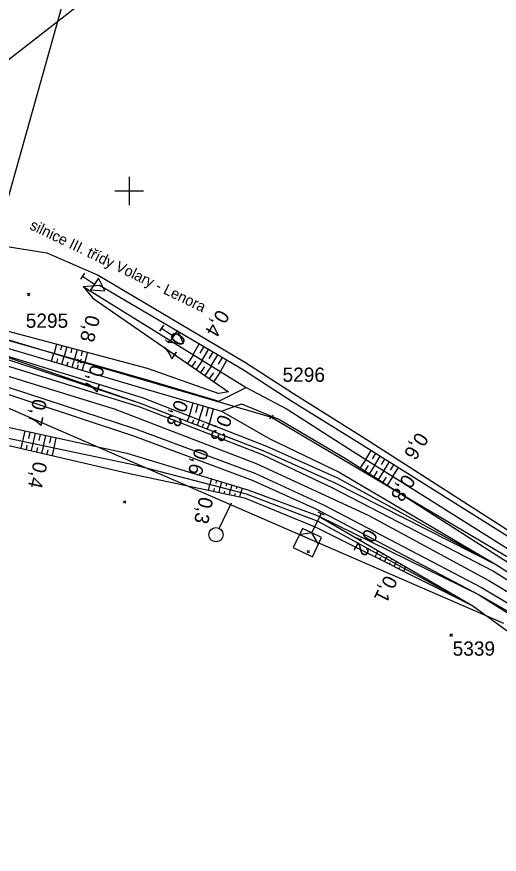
# Model space of a CAD drawing. Extents: x -804899 to -803847, y -1165742 to -1164942.
# Drawn here: x -804715.8 to -804648, y -1165193.1 to -1165075.5 of the extents above; entities that cross this region are included whole.
import ezdxf

# ---------------------------------------------------------------- set-up
doc = ezdxf.new("R2010")
doc.units = 0
for name, color, linetype in [('0381KM061-064P - Vrstva 1', 7, 'Continuous'), ('0381KM061-064P - Vrstva 36', 7, 'Continuous'), ('0381KM061-064P - Vrstva 4', 7, 'Continuous'), ('0381KM061-064P - Vrstva 48', 7, 'Continuous'), ('0381KM061-064P - Vrstva 49', 7, 'Continuous'), ('0381KM061-064P - Vrstva 51', 7, 'Continuous'), ('0381KM061-064P - Vrstva 55', 7, 'Continuous'), ('0381KM061-064P - Vrstva 7', 7, 'Continuous'), ('0381KM061-064P - Vrstva 8', 7, 'Continuous'), ('krizky_1000 - Vrstva 1', 7, 'Continuous'), ('szdc - hran DP', 7, 'Continuous'), ('szdc - szdc_cislo', 7, 'Continuous'), ('szdc - szdc_krizek', 7, 'Continuous')]:
    doc.layers.add(name, color=color, linetype=linetype)

msp = doc.modelspace()

# ---------------------------------------------------------------- linework, layer by layer
at = {"layer": '0381KM061-064P - Vrstva 1'}
for points in [[(-804748.02, -1165118.72), (-804737.69, -1165120.7), (-804722.06, -1165124.43), (-804702.11, -1165130.56), (-804682.19, -1165138.24), (-804666.44, -1165145.5)], [(-804666.44, -1165145.5), (-804649.48, -1165154.65), (-804645.14, -1165157.27), (-804633.7, -1165164.38), (-804619.36, -1165173.74)]]:
    msp.add_lwpolyline(points, dxfattribs=at)
at = {"layer": '0381KM061-064P - Vrstva 36'}
for p, q in [((-804687.37, -1165147.34), (-804685.62, -1165143.74)), ((-804687.81, -1165148.24), (-804687.81, -1165148.24))]:
    msp.add_line(p, q, dxfattribs=at)
msp.add_circle((-804687.81, -1165148.24), 1, dxfattribs=at)
at = {"layer": '0381KM061-064P - Vrstva 4'}
for points in [[(-804755.73, -1165115.93), (-804748.17, -1165116.91), (-804721.25, -1165123.25), (-804698.66, -1165130.22), (-804681.33, -1165136.99), (-804671.47, -1165141.65), (-804648.84, -1165153.36), (-804638.11, -1165160.03), (-804624.48, -1165168.7), (-804602.56, -1165183.07), (-804574.47, -1165201.72), (-804542.72, -1165222.84), (-804507.36, -1165246.55), (-804477.08, -1165266.82), (-804448.75, -1165285.88), (-804421.18, -1165304.15), (-804392.89, -1165323.09), (-804369.85, -1165338.37), (-804348.86, -1165352.04), (-804325.13, -1165367.98), (-804299.32, -1165385.27), (-804266.05, -1165407.31), (-804234.28, -1165428.6)], [(-804755.73, -1165115.93), (-804748.03, -1165116.49), (-804721.05, -1165122.36), (-804698.44, -1165129.77), (-804680.98, -1165136.5), (-804671.21, -1165140.89), (-804648.42, -1165152.46), (-804637.55, -1165159.43), (-804624.04, -1165168.29), (-804602.25, -1165182.38), (-804573.74, -1165201.2), (-804542.46, -1165222.56), (-804507.06, -1165246.03), (-804476.47, -1165266.24), (-804448.31, -1165285.08), (-804421.02, -1165303.1), (-804392.59, -1165322.59), (-804369.41, -1165337.65), (-804348.68, -1165351.59), (-804324.76, -1165367.42), (-804298.9, -1165384.42), (-804265.65, -1165406.5), (-804234.05, -1165428.04)], [(-804760.26, -1165118.8), (-804748.36, -1165120.01), (-804721.79, -1165126), (-804699.13, -1165133.38), (-804682.38, -1165139.58), (-804672.62, -1165144.09), (-804650.43, -1165155.7), (-804639.38, -1165162.29), (-804626.13, -1165170.89), (-804604.37, -1165185.52), (-804576.36, -1165204.15)], [(-804760.26, -1165118.8), (-804748.39, -1165120.75), (-804721.77, -1165126.98), (-804699.38, -1165134.38), (-804682.72, -1165140.57), (-804673.68, -1165144.67), (-804650.96, -1165156.64), (-804639.65, -1165163.02), (-804626.64, -1165171.43)]]:
    msp.add_lwpolyline(points, dxfattribs=at)
at = {"layer": '0381KM061-064P - Vrstva 48'}
for p, q in [((-804710.21, -1165121.48), (-804710.55, -1165122.77)), ((-804709.48, -1165121.67), (-804709.66, -1165122.33)), ((-804708.76, -1165121.87), (-804709.11, -1165123.18)), ((-804708.03, -1165122.06), (-804708.21, -1165122.72)), ((-804707.31, -1165122.25), (-804707.66, -1165123.59)), ((-804691.03, -1165122.96), (-804690.15, -1165121.47)), ((-804690.04, -1165122.75), (-804689.51, -1165121.85)), ((-804689.75, -1165123.74), (-804688.86, -1165122.23)), ((-804710.9, -1165123.89), (-804710.57, -1165122.77)), ((-804710.18, -1165124.1), (-804710.01, -1165123.54)), ((-804709.46, -1165124.31), (-804709.13, -1165123.18)), ((-804708.02, -1165124.74), (-804707.68, -1165123.59)), ((-804706.58, -1165122.44), (-804706.76, -1165123.12)), ((-804705.86, -1165122.63), (-804706.22, -1165124)), ((-804690.99, -1165122.98), (-804691.83, -1165124.19)), ((-804688.75, -1165123.53), (-804688.21, -1165122.61)), ((-804688.47, -1165124.53), (-804687.57, -1165122.99)), ((-804687.47, -1165124.3), (-804686.92, -1165123.37)), ((-804708.74, -1165124.53), (-804708.57, -1165123.96)), ((-804707.31, -1165124.95), (-804707.13, -1165124.37)), ((-804706.59, -1165125.17), (-804706.24, -1165124)), ((-804690.7, -1165123.87), (-804691.22, -1165124.62)), ((-804689.72, -1165123.76), (-804690.6, -1165125.04)), ((-804689.44, -1165124.68), (-804689.98, -1165125.47)), ((-804688.44, -1165124.55), (-804689.36, -1165125.9)), ((-804687.2, -1165125.32), (-804686.28, -1165123.75)), ((-804688.18, -1165125.5), (-804688.75, -1165126.32)), ((-804687.16, -1165125.34), (-804688.13, -1165126.75)), ((-804691.55, -1165131.57), (-804691.02, -1165129.73)), ((-804690.63, -1165131.08), (-804690.3, -1165129.93)), ((-804690.15, -1165132.12), (-804689.58, -1165130.14)), ((-804689.21, -1165131.58), (-804688.85, -1165130.35)), ((-804688.74, -1165132.67), (-804688.14, -1165130.56)), ((-804691.55, -1165131.57), (-804691.84, -1165132.32)), ((-804690.97, -1165132.14), (-804691.14, -1165132.59)), ((-804690.15, -1165132.12), (-804690.44, -1165132.86)), ((-804689.57, -1165132.69), (-804689.74, -1165133.13)), ((-804688.76, -1165132.67), (-804689.04, -1165133.4)), ((-804714.95, -1165135.13), (-804714.62, -1165133.68)), ((-804714.08, -1165134.71), (-804713.89, -1165133.84)), ((-804713.48, -1165135.44), (-804713.16, -1165134)), ((-804712.62, -1165135.02), (-804712.43, -1165134.16)), ((-804714.99, -1165135.12), (-804715.21, -1165136.09)), ((-804712.01, -1165135.75), (-804711.7, -1165134.32)), ((-804711.15, -1165135.34), (-804710.97, -1165134.48)), ((-804710.55, -1165136.06), (-804710.23, -1165134.64)), ((-804714.35, -1165135.67), (-804714.48, -1165136.27)), ((-804713.52, -1165135.43), (-804713.75, -1165136.43)), ((-804712.88, -1165136), (-804713.02, -1165136.6)), ((-804712.05, -1165135.74), (-804712.29, -1165136.77)), ((-804711.42, -1165136.32), (-804711.56, -1165136.94)), ((-804710.59, -1165136.05), (-804710.83, -1165137.11)), ((-804666.78, -1165137.66), (-804666.01, -1165136.43)), ((-804666.78, -1165137.66), (-804667.55, -1165138.86)), ((-804665.84, -1165137.57), (-804665.37, -1165136.83)), ((-804665.51, -1165138.46), (-804664.74, -1165137.23)), ((-804664.57, -1165138.36), (-804664.1, -1165137.62)), ((-804666.45, -1165138.54), (-804666.91, -1165139.26)), ((-804665.51, -1165138.46), (-804666.28, -1165139.67)), ((-804664.24, -1165139.26), (-804663.47, -1165138.02)), ((-804663.3, -1165139.16), (-804662.83, -1165138.42)), ((-804662.97, -1165140.05), (-804662.2, -1165138.82)), ((-804665.18, -1165139.34), (-804665.65, -1165140.07)), ((-804664.24, -1165139.26), (-804665.02, -1165140.48)), ((-804662.97, -1165140.05), (-804663.76, -1165141.29)), ((-804688.84, -1165142.01), (-804688.66, -1165141.19)), ((-804688.46, -1165140.41), (-804688.69, -1165141.18)), ((-804687.74, -1165140.63), (-804687.85, -1165141)), ((-804687.02, -1165140.85), (-804687.24, -1165141.55)), ((-804686.31, -1165141.06), (-804686.41, -1165141.4)), ((-804663.92, -1165140.15), (-804664.39, -1165140.88)), ((-804688.1, -1165142.16), (-804688.02, -1165141.77)), ((-804687.37, -1165142.32), (-804687.21, -1165141.56)), ((-804686.64, -1165142.48), (-804686.56, -1165142.11)), ((-804685.9, -1165142.63), (-804685.76, -1165141.94)), ((-804685.59, -1165141.28), (-804685.78, -1165141.93)), ((-804684.87, -1165141.5), (-804684.96, -1165141.81)), ((-804684.44, -1165142.95), (-804684.3, -1165142.31)), ((-804684.15, -1165141.72), (-804684.33, -1165142.31)), ((-804685.17, -1165142.79), (-804685.1, -1165142.46)), ((-804665.07, -1165150.48), (-804665.27, -1165150.82)), ((-804665.47, -1165151.34), (-804665.22, -1165150.85)), ((-804664.8, -1165151.68), (-804664.68, -1165151.44)), ((-804664.42, -1165150.85), (-804664.52, -1165151.02)), ((-804664.13, -1165152.01), (-804663.91, -1165151.57)), ((-804663.77, -1165151.23), (-804663.96, -1165151.54)), ((-804663.13, -1165151.61), (-804663.21, -1165151.75)), ((-804663.46, -1165152.35), (-804663.35, -1165152.14)), ((-804662.79, -1165152.68), (-804662.59, -1165152.29)), ((-804662.48, -1165151.98), (-804662.64, -1165152.26)), ((-804662.12, -1165153.02), (-804662.02, -1165152.83)), ((-804661.83, -1165152.36), (-804661.9, -1165152.49)), ((-804661.18, -1165152.74), (-804661.32, -1165152.98)), ((-804661.45, -1165153.35), (-804661.27, -1165153.01))]:
    msp.add_line(p, q, dxfattribs=at)
at = {"layer": '0381KM061-064P - Vrstva 49'}
for p, q in [((-804713.94, -1165114.69), (-804714.29, -1165114.34)), ((-804713.94, -1165114.34), (-804714.29, -1165114.69)), ((-804700.46, -1165143.82), (-804700.81, -1165143.47)), ((-804700.46, -1165143.47), (-804700.81, -1165143.82)), ((-804673.48, -1165145.6), (-804650.96, -1165156.64)), ((-804674.66, -1165150.8), (-804675.01, -1165150.45)), ((-804674.66, -1165150.45), (-804675.01, -1165150.8)), ((-804654.61, -1165162.53), (-804654.97, -1165162.18)), ((-804654.61, -1165162.18), (-804654.97, -1165162.53))]:
    msp.add_line(p, q, dxfattribs=at)
for points in [[(-804755.73, -1165115.93), (-804751.24, -1165112.25), (-804747.15, -1165112.99), (-804720.56, -1165118.75), (-804697.46, -1165124.86)], [(-804706.48, -1165113.41), (-804704.19, -1165113.22), (-804684.11, -1165125.02), (-804677.29, -1165129.42), (-804668.09, -1165135.13)], [(-804706.48, -1165113.41), (-804683.56, -1165127.57)], [(-804706.48, -1165113.41), (-804705.1, -1165115.06), (-804686.07, -1165128.17), (-804687.41, -1165128.4)], [(-804754.42, -1165115.02), (-804748.04, -1165114.39), (-804721.19, -1165119.75), (-804697.28, -1165126.54)], [(-804755.73, -1165115.93), (-804747.85, -1165115.39), (-804738.73, -1165116.75), (-804720.93, -1165120.92), (-804697.63, -1165127.82)], [(-804738.73, -1165116.75), (-804737.5, -1165118.13), (-804721.08, -1165121.98), (-804698.17, -1165128.96), (-804680.73, -1165135.83), (-804670.75, -1165140.27), (-804648.42, -1165152.46)], [(-804721.08, -1165121.98), (-804698.44, -1165129.77), (-804680.98, -1165136.5), (-804671.21, -1165140.89), (-804648.42, -1165152.46)], [(-804766.83, -1165123.91), (-804764.89, -1165122.96), (-804750.44, -1165127.42), (-804724.29, -1165131.56), (-804700.35, -1165136.81), (-804683.35, -1165141.96), (-804673.48, -1165145.6), (-804651.73, -1165158.22)], [(-804766.32, -1165124.35), (-804750.31, -1165128.3), (-804724.8, -1165133.06), (-804699.44, -1165138.4), (-804683.58, -1165142.5), (-804673.52, -1165146.32), (-804651.73, -1165158.22)], [(-804697.46, -1165124.86), (-804687.41, -1165128.4)], [(-804697.28, -1165126.54), (-804687.39, -1165129.5), (-804683.56, -1165127.57)], [(-804697.63, -1165127.82), (-804687.02, -1165130.88), (-804684.24, -1165129.87), (-804678.91, -1165132.05), (-804669.51, -1165137.6)], [(-804683.56, -1165127.57), (-804677.8, -1165130.64), (-804668.53, -1165136.56)], [(-804687.02, -1165130.88), (-804680.25, -1165134.76), (-804670.53, -1165139.48)], [(-804724.99, -1165133.83), (-804700.39, -1165139.54), (-804683.82, -1165143.08), (-804673.79, -1165147.18), (-804651.73, -1165158.22)], [(-804668.09, -1165135.13), (-804646.08, -1165148.91), (-804635.34, -1165155.79), (-804621.98, -1165164.4), (-804599.68, -1165178.86), (-804570.23, -1165197.63), (-804539.04, -1165217.4), (-804503.79, -1165239.32), (-804473.21, -1165259.25), (-804445.02, -1165277.37), (-804416.3, -1165295.6), (-804385.23, -1165314.87), (-804342.84, -1165342.16), (-804322.16, -1165355.5), (-804292.15, -1165374.6), (-804262.58, -1165393.44), (-804234.25, -1165411.43)], [(-804669.51, -1165137.6), (-804647.83, -1165151.5), (-804636.87, -1165158.28), (-804626.96, -1165165.56)], [(-804668.53, -1165136.56), (-804646.51, -1165150.38), (-804635.75, -1165157.19), (-804622.88, -1165165.28), (-804600.74, -1165180), (-804571.06, -1165199.05), (-804539.91, -1165219.23), (-804504.85, -1165241.38), (-804474.07, -1165260.59), (-804445.75, -1165278.86), (-804417.38, -1165297.08), (-804386.13, -1165316.29), (-804343.68, -1165343.22), (-804323.05, -1165356.81), (-804293.41, -1165375.48), (-804263.45, -1165394.43), (-804234.68, -1165412.78)], [(-804670.53, -1165139.48), (-804648.42, -1165152.46)], [(-804650.96, -1165156.64), (-804629.95, -1165169.87)], [(-804651.73, -1165158.22), (-804641.24, -1165165.82), (-804629.21, -1165174.28), (-804606.38, -1165188.59), (-804578.69, -1165207.38), (-804546.55, -1165228.41), (-804509.4, -1165252.77), (-804482.02, -1165272.35), (-804454.07, -1165289.87), (-804424.02, -1165310.32)]]:
    msp.add_lwpolyline(points, dxfattribs=at)
at = {"layer": '0381KM061-064P - Vrstva 51'}
for p, q in [((-804706.26, -1165111.53), (-804706.82, -1165112.36)), ((-804695.16, -1165118.83), (-804695.73, -1165119.65))]:
    msp.add_line(p, q, dxfattribs=at)
for points in [[(-804728.9, -1165105.9), (-804711.54, -1165108.67), (-804704.35, -1165111.8), (-804683.69, -1165124.09), (-804676.95, -1165128.43), (-804667.36, -1165134.41), (-804645.71, -1165148.3), (-804634.7, -1165155.23), (-804621.63, -1165163.62), (-804599.19, -1165178.23), (-804569.67, -1165197.16), (-804538.42, -1165216.77), (-804503.41, -1165238.94), (-804472.82, -1165258.55), (-804444.57, -1165276.4), (-804415.82, -1165294.73), (-804384.7, -1165314.57), (-804342.59, -1165341.72), (-804321.8, -1165355.02), (-804291.77, -1165374.22), (-804262.45, -1165392.96)], [(-804706.54, -1165111.95), (-804704.88, -1165113.06), (-804705.43, -1165113.89), (-804703.42, -1165114.03), (-804704.32, -1165112.23), (-804704.88, -1165113.06)], [(-804695.45, -1165119.24), (-804693.8, -1165120.39), (-804694.38, -1165121.21), (-804692.37, -1165121.39), (-804693.23, -1165119.57), (-804693.8, -1165120.39)]]:
    msp.add_lwpolyline(points, dxfattribs=at)
at = {"layer": '0381KM061-064P - Vrstva 55'}
msp.add_lwpolyline([(-804834.02, -1165173.21), (-804777.95, -1165165.95), (-804761.65, -1165133.49), (-804755.48, -1165121.19), (-804751.26, -1165114.04), (-804741.92, -1165100.8), (-804736.13, -1165096.49), (-804701.79, -1165069.72), (-804628.3, -1165012.44)], dxfattribs=at)
at = {"layer": '0381KM061-064P - Vrstva 7'}
for p, q in [((-804674.33, -1165147.99), (-804673.03, -1165145.29)), ((-804672.58, -1165145.51), (-804673.48, -1165145.07))]:
    msp.add_line(p, q, dxfattribs=at)
for points in [[(-804674.33, -1165147.99), (-804675.68, -1165147.34), (-804676.99, -1165150.04), (-804674.28, -1165151.35), (-804672.98, -1165148.64), (-804674.33, -1165147.99)], [(-804673.42, -1165149.55), (-804674.33, -1165147.99), (-804676.12, -1165148.24)]]:
    msp.add_lwpolyline(points, dxfattribs=at)
at = {"layer": '0381KM061-064P - Vrstva 8'}
msp.add_line((-804722.5, -1165120.54), (-804702.47, -1165049.27), dxfattribs=at)
at = {"layer": 'krizky_1000 - Vrstva 1'}
for points in [[(-804700, -1165098), (-804700, -1165102)], [(-804702, -1165100), (-804698, -1165100)]]:
    msp.add_lwpolyline(points, dxfattribs=at)
at = {"layer": 'szdc - hran DP'}
for p, q in [((-804735.44, -1165115.31), (-804706.98, -1165123.89)), ((-804706.98, -1165123.89), (-804680.02, -1165131.72)), ((-804647.39, -1165160.7), (-804728.07, -1165125.68)), ((-804680.02, -1165131.72), (-804619.47, -1165167.61))]:
    msp.add_line(p, q, dxfattribs=at)
at = {"layer": 'szdc - szdc_krizek'}
for p, q in [((-804706.71, -1165124.16), (-804707.25, -1165123.62)), ((-804707.25, -1165124.16), (-804706.71, -1165123.62)), ((-804679.76, -1165131.99), (-804680.29, -1165131.46)), ((-804680.29, -1165131.99), (-804679.76, -1165131.46))]:
    msp.add_line(p, q, dxfattribs=at)

# ---------------------------------------------------------------- texts
at = {"layer": '0381KM061-064P - Vrstva 48'}
for s, rotation, p in [('0,8', 255.1809, (-804705.99, -1165117.28)), ('0,4', 239.5582, (-804687.53, -1165116.49)), ('0,7', 235.4402, (-804693.57, -1165119.56)), ('0,7', 253.4991, (-804705.33, -1165124.27)), ('0,7', 257.6347, (-804713.48, -1165129.05)), ('0,3', 248.475, (-804693.49, -1165129.14)), ('0,3', 248.9077, (-804687.35, -1165131.22)), ('0,6', 237.9371, (-804659.53, -1165133.71)), ('0,6', 253.1416, (-804690.71, -1165135.94)), ('0,4', 256.9301, (-804713.4, -1165137.84)), ('0,8', 237.3341, (-804661.36, -1165139.59)), ('0,3', 257.9404, (-804690.13, -1165142.82)), ('0,2', 239.8871, (-804666.72, -1165147.24)), ('0,1', 243.4194, (-804664.02, -1165153.78))]:
    msp.add_text(s, height=2, rotation=rotation, dxfattribs=at).set_placement(p)
at = {"layer": '0381KM061-064P - Vrstva 51'}
msp.add_text('silnice III. třídy Volary - Lenora', height=1.5, rotation=334.2578, dxfattribs=at).set_placement((-804714.1, -1165105.29))
at = {"layer": 'szdc - szdc_cislo'}
for s, p in [('5295', (-804714.52, -1165119.2)), ('5296', (-804678.46, -1165126.78)), ('5339', (-804654.58, -1165165.21))]:
    msp.add_text(s, height=2, dxfattribs=at).set_placement(p)

doc.saveas('drawing.dxf')
